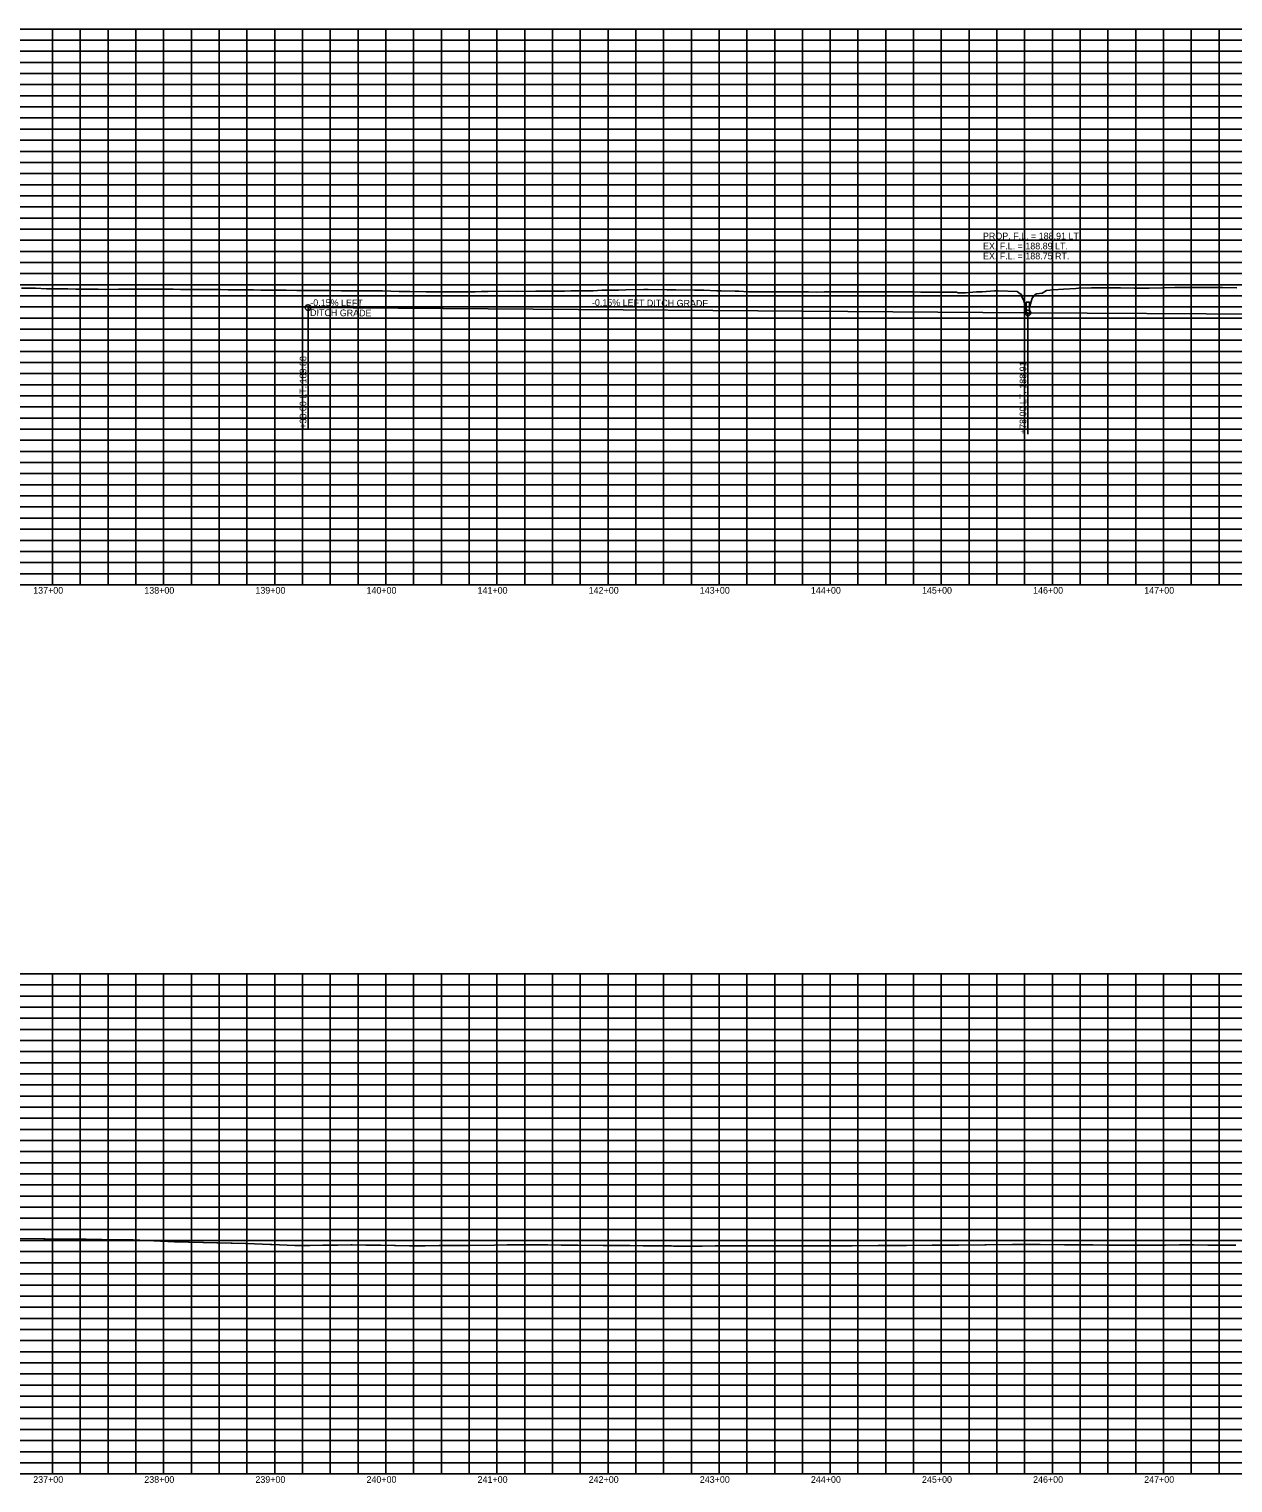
# Model space of a CAD drawing. Extents: x 1399671 to 1408349, y 1930471 to 1933387.
# Drawn here: x 1404003 to 1405087, y 1932071 to 1933379 of the extents above; entities that cross this region are included whole.
import ezdxf

# ---------------------------------------------------------------- set-up
doc = ezdxf.new("R2010")
doc.units = 0
for name, color, linetype in [('R_Drainage', 7, 'Continuous'), ('R_Exist Surface', 7, 'Continuous'), ('R_Grid', 7, 'Continuous'), ('R_Grid Annot', 7, 'Continuous'), ('R_Vert Alg', 7, 'Continuous'), ('R_Vert Alg Annot', 7, 'Continuous')]:
    doc.layers.add(name, color=color, linetype=linetype)

msp = doc.modelspace()

# ---------------------------------------------------------------- linework, layer by layer
at = {"layer": 'R_Drainage'}
msp.add_lwpolyline([(1404900.7, 1933122.8), (1404903.7, 1933122.8), (1404903.7, 1933132.8), (1404900.7, 1933132.8)], close=True, dxfattribs=at)
at = {"layer": 'R_Exist Surface'}
for points in [[(1403996.4, 1933145.6), (1404008.9, 1933145.5), (1404018.7, 1933145), (1404024.5, 1933145), (1404032, 1933144.9), (1404038.1, 1933144.8), (1404045.3, 1933144.7), (1404051.7, 1933144.6), (1404058.7, 1933144.5), (1404065.3, 1933144.5), (1404072, 1933144.4), (1404083.5, 1933144.5), (1404095.3, 1933144.5), (1404106.6, 1933144.6), (1404118.6, 1933144.6), (1404125.4, 1933144.5), (1404132.8, 1933144.5), (1404139.5, 1933144.4), (1404147, 1933144.4), (1404153.6, 1933144.4), (1404161.2, 1933144.3), (1404167.8, 1933144.3), (1404175.4, 1933144.2), (1404182.3, 1933144.1), (1404190.2, 1933144.1), (1404197, 1933144), (1404205, 1933143.9), (1404211.8, 1933143.8), (1404219.8, 1933143.8), (1404226.5, 1933143.7), (1404234.6, 1933143.6), (1404244, 1933143.5), (1404253.9, 1933143.5), (1404264, 1933143.4), (1404273.2, 1933143.4), (1404284.2, 1933143.2), (1404292.5, 1933143.2), (1404300.8, 1933143.2), (1404311.9, 1933143), (1404321.1, 1933143), (1404336.2, 1933142.6), (1404346, 1933142.6), (1404360.6, 1933142.2), (1404366.1, 1933142.2), (1404379.9, 1933142.2), (1404385.4, 1933142.2), (1404390.8, 1933142.3), (1404404.7, 1933142.2), (1404410, 1933142.6), (1404416.3, 1933142.5), (1404434.6, 1933142.7), (1404442.7, 1933142.5), (1404459.2, 1933142.7), (1404464.5, 1933142.7), (1404472.1, 1933142.8), (1404477.6, 1933142.8), (1404485, 1933142.9), (1404490.6, 1933143), (1404497.9, 1933143), (1404503.7, 1933143.1), (1404510.8, 1933143.1), (1404518.7, 1933143.6), (1404533.5, 1933143.8), (1404540.2, 1933144.1), (1404556.4, 1933144.4), (1404560.3, 1933144.3), (1404577.3, 1933144.1), (1404581.3, 1933144), (1404585.3, 1933143.9), (1404602, 1933143.7), (1404606.1, 1933143.6), (1404610.3, 1933143.6), (1404622.1, 1933143.2), (1404625.9, 1933143.2), (1404638.5, 1933142.8), (1404641.8, 1933142.8), (1404650.7, 1933142.3), (1404656.6, 1933142.3), (1404663.9, 1933142.3), (1404670.3, 1933142.2), (1404677.6, 1933142.2), (1404684.1, 1933142.2), (1404691.2, 1933142.1), (1404697.8, 1933142.1), (1404704.8, 1933142.1), (1404711.5, 1933142), (1404718.9, 1933142.1), (1404725.7, 1933142.1), (1404733, 1933142.1), (1404739.8, 1933142.1), (1404747.1, 1933142.2), (1404753.9, 1933142.2), (1404760.8, 1933142.2), (1404768.1, 1933142.2), (1404774.2, 1933142.2), (1404780.7, 1933142.2), (1404786.8, 1933142.1), (1404793.2, 1933142.1), (1404799.3, 1933142.1), (1404805.8, 1933142), (1404811.9, 1933142), (1404818.4, 1933142), (1404826.9, 1933141.9), (1404837.9, 1933141.8), (1404839.4, 1933141.4), (1404846, 1933141.4), (1404855.9, 1933142.1), (1404861.1, 1933142.1), (1404872.1, 1933143.1), (1404875.5, 1933143.1), (1404892.6, 1933142.6), (1404895.3, 1933140.3), (1404896.3, 1933139.9), (1404896.8, 1933138), (1404898.5, 1933134.2), (1404899.6, 1933130), (1404901.8, 1933128.8), (1404903.8, 1933129.4), (1404905, 1933133.5), (1404905.9, 1933136.4), (1404908.4, 1933139.4), (1404910, 1933140.5), (1404915, 1933141), (1404918.9, 1933143.4), (1404924.9, 1933144.1), (1404934.2, 1933144.6), (1404945.3, 1933145.1), (1404947.7, 1933145.4), (1404959.3, 1933145.8), (1404959.5, 1933145.8), (1404972.1, 1933145.8), (1404972.4, 1933145.8), (1404985, 1933145.7), (1404985.4, 1933145.7), (1404997.8, 1933145.6), (1404998.4, 1933145.6), (1405010.6, 1933145.5), (1405011.4, 1933145.5), (1405024.1, 1933145.8), (1405024.4, 1933145.8), (1405034.4, 1933146), (1405037.4, 1933146), (1405037.5, 1933146), (1405050.1, 1933146.1), (1405051, 1933146.1), (1405051.9, 1933146.1), (1405064.4, 1933146.1), (1405076.6, 1933146), (1405077.4, 1933146), (1405090.1, 1933145.8)], [(1403993.9, 1932290.5), (1404016.3, 1932290.2), (1404017.3, 1932290.2), (1404040, 1932289.9), (1404040.5, 1932289.9), (1404054, 1932289.7), (1404054.5, 1932289.7), (1404068.1, 1932289.5), (1404068.6, 1932289.5), (1404082.2, 1932289.3), (1404082.7, 1932289.3), (1404096.2, 1932289.1), (1404096.7, 1932289.1), (1404108.8, 1932288.6), (1404109.3, 1932288.6), (1404121.4, 1932288.1), (1404122, 1932288), (1404133.9, 1932287.5), (1404134.6, 1932287.5), (1404146.5, 1932287), (1404147.3, 1932287), (1404159.4, 1932286.7), (1404160.1, 1932286.7), (1404172.2, 1932286.4), (1404172.9, 1932286.4), (1404185.1, 1932286.1), (1404185.8, 1932286.1), (1404198, 1932285.9), (1404199.2, 1932285.8), (1404220.1, 1932285), (1404221.6, 1932285), (1404242.3, 1932284.1), (1404243.2, 1932284.1), (1404254.9, 1932284.2), (1404255.8, 1932284.2), (1404267.6, 1932284.4), (1404268.5, 1932284.4), (1404280.2, 1932284.5), (1404281.1, 1932284.5), (1404292.8, 1932284.6), (1404293.8, 1932284.6), (1404306.2, 1932284.4), (1404307.2, 1932284.4), (1404319.6, 1932284.3), (1404332.1, 1932284.1), (1404333, 1932284.1), (1404345.4, 1932283.9), (1404346.4, 1932283.9), (1404358.8, 1932283.9), (1404359.6, 1932283.9), (1404372.1, 1932284), (1404372.8, 1932284), (1404373.5, 1932284), (1404386, 1932284.1), (1404386.6, 1932284.1), (1404399.2, 1932284.2), (1404400.2, 1932284.2), (1404421.9, 1932284.5), (1404433.5, 1932284.6), (1404443.3, 1932284.8), (1404444.5, 1932284.8), (1404456.6, 1932284.7), (1404457.9, 1932284.7), (1404470.1, 1932284.6), (1404482.1, 1932284.5), (1404483.5, 1932284.5), (1404495.6, 1932284.4), (1404497.1, 1932284.4), (1404519.7, 1932284.2), (1404521.3, 1932284.2), (1404543.8, 1932284.1), (1404555.8, 1932283.9), (1404557.5, 1932283.9), (1404569.4, 1932283.8), (1404581.3, 1932283.7), (1404583.2, 1932283.6), (1404595, 1932283.5), (1404596.1, 1932283.5), (1404607.9, 1932283.6), (1404608.9, 1932283.6), (1404620.7, 1932283.7), (1404621.8, 1932283.7), (1404633.5, 1932283.8), (1404634.6, 1932283.8), (1404646.4, 1932283.9), (1404648.4, 1932283.9), (1404670.1, 1932283.9), (1404671.6, 1932283.9), (1404693.8, 1932283.9), (1404694.3, 1932283.9), (1404717.9, 1932283.9), (1404718.4, 1932283.9), (1404719, 1932283.9), (1404742.6, 1932283.8), (1404743.1, 1932283.8), (1404744.1, 1932283.8), (1404767.5, 1932284), (1404768.5, 1932284), (1404792, 1932284.1), (1404792.9, 1932284.1), (1404815.9, 1932284.3), (1404838.8, 1932284.5), (1404839.9, 1932284.5), (1404863.5, 1932284.8), (1404864.6, 1932284.8), (1404888.2, 1932285.1), (1404889.2, 1932285.1), (1404911.2, 1932285), (1404912.2, 1932284.9), (1404913.2, 1932284.9), (1404935.2, 1932284.8), (1404935.7, 1932284.8), (1404948, 1932284.7), (1404960.1, 1932284.6), (1404960.7, 1932284.6), (1404972.9, 1932284.5), (1404973.5, 1932284.5), (1404985.6, 1932284.5), (1404986.3, 1932284.5), (1404998.8, 1932284.5), (1404999.3, 1932284.5), (1404999.9, 1932284.5), (1405012.4, 1932284.5), (1405012.9, 1932284.5), (1405025.5, 1932284.5), (1405025.9, 1932284.5), (1405038.5, 1932284.6), (1405038.9, 1932284.6), (1405051.3, 1932284.6), (1405051.6, 1932284.6), (1405064.1, 1932284.5), (1405076.5, 1932284.5), (1405076.8, 1932284.5), (1405089.3, 1932284.5)]]:
    msp.add_lwpolyline(points, dxfattribs=at)
at = {"layer": 'R_Grid'}
for p, q in [((1400324.2, 1933378.6), (1408224.2, 1933378.6)), ((1400324.2, 1933378.6), (1408224.2, 1933378.6)), ((1404024.2, 1932878.6), (1404024.2, 1933378.6)), ((1404049.2, 1932878.6), (1404049.2, 1933378.6)), ((1404074.2, 1932878.6), (1404074.2, 1933378.6)), ((1404099.2, 1932878.6), (1404099.2, 1933378.6)), ((1404124.2, 1932878.6), (1404124.2, 1933378.6)), ((1404149.2, 1932878.6), (1404149.2, 1933378.6)), ((1404174.2, 1932878.6), (1404174.2, 1933378.6)), ((1404199.2, 1932878.6), (1404199.2, 1933378.6)), ((1404224.2, 1932878.6), (1404224.2, 1933378.6)), ((1404249.2, 1932878.6), (1404249.2, 1933378.6)), ((1404274.2, 1932878.6), (1404274.2, 1933378.6)), ((1404299.2, 1932878.6), (1404299.2, 1933378.6)), ((1404324.2, 1932878.6), (1404324.2, 1933378.6)), ((1404349.2, 1932878.6), (1404349.2, 1933378.6)), ((1404374.2, 1932878.6), (1404374.2, 1933378.6)), ((1404399.2, 1932878.6), (1404399.2, 1933378.6)), ((1404424.2, 1932878.6), (1404424.2, 1933378.6)), ((1404449.2, 1932878.6), (1404449.2, 1933378.6)), ((1404474.2, 1932878.6), (1404474.2, 1933378.6)), ((1404499.2, 1932878.6), (1404499.2, 1933378.6)), ((1404524.2, 1932878.6), (1404524.2, 1933378.6)), ((1404549.2, 1932878.6), (1404549.2, 1933378.6)), ((1404574.2, 1932878.6), (1404574.2, 1933378.6)), ((1404599.2, 1932878.6), (1404599.2, 1933378.6)), ((1404624.2, 1932878.6), (1404624.2, 1933378.6)), ((1404649.2, 1932878.6), (1404649.2, 1933378.6)), ((1404674.2, 1932878.6), (1404674.2, 1933378.6)), ((1404699.2, 1932878.6), (1404699.2, 1933378.6)), ((1404724.2, 1932878.6), (1404724.2, 1933378.6)), ((1404749.2, 1932878.6), (1404749.2, 1933378.6)), ((1404774.2, 1932878.6), (1404774.2, 1933378.6)), ((1404799.2, 1932878.6), (1404799.2, 1933378.6)), ((1404824.2, 1932878.6), (1404824.2, 1933378.6)), ((1404849.2, 1932878.6), (1404849.2, 1933378.6)), ((1404874.2, 1932878.6), (1404874.2, 1933378.6)), ((1404899.2, 1932878.6), (1404899.2, 1933378.6)), ((1404924.2, 1932878.6), (1404924.2, 1933378.6)), ((1404949.2, 1932878.6), (1404949.2, 1933378.6)), ((1404974.2, 1932878.6), (1404974.2, 1933378.6)), ((1404999.2, 1932878.6), (1404999.2, 1933378.6)), ((1405024.2, 1932878.6), (1405024.2, 1933378.6)), ((1405049.2, 1932878.6), (1405049.2, 1933378.6)), ((1405074.2, 1932878.6), (1405074.2, 1933378.6)), ((1400324.2, 1933368.6), (1408224.2, 1933368.6)), ((1400324.2, 1933358.6), (1408224.2, 1933358.6)), ((1400324.2, 1933348.6), (1408224.2, 1933348.6)), ((1400324.2, 1933338.6), (1408224.2, 1933338.6)), ((1400324.2, 1933328.6), (1408224.2, 1933328.6)), ((1400324.2, 1933318.6), (1408224.2, 1933318.6)), ((1400324.2, 1933308.6), (1408224.2, 1933308.6)), ((1400324.2, 1933298.6), (1408224.2, 1933298.6)), ((1400324.2, 1933288.6), (1408224.2, 1933288.6)), ((1400324.2, 1933278.6), (1408224.2, 1933278.6)), ((1400324.2, 1933268.6), (1408224.2, 1933268.6)), ((1400324.2, 1933258.6), (1408224.2, 1933258.6)), ((1400324.2, 1933248.6), (1408224.2, 1933248.6)), ((1400324.2, 1933238.6), (1408224.2, 1933238.6)), ((1400324.2, 1933228.6), (1408224.2, 1933228.6)), ((1400324.2, 1933218.6), (1408224.2, 1933218.6)), ((1400324.2, 1933208.6), (1408224.2, 1933208.6)), ((1400324.2, 1933198.6), (1408224.2, 1933198.6)), ((1400324.2, 1933188.6), (1408224.2, 1933188.6)), ((1400324.2, 1933178.6), (1408224.2, 1933178.6)), ((1400324.2, 1933168.6), (1408224.2, 1933168.6)), ((1400324.2, 1933158.6), (1408224.2, 1933158.6)), ((1400324.2, 1933148.6), (1408224.2, 1933148.6)), ((1400324.2, 1933138.6), (1408224.2, 1933138.6)), ((1400324.2, 1933128.6), (1408224.2, 1933128.6)), ((1400324.2, 1933118.6), (1408224.2, 1933118.6)), ((1400324.2, 1933108.6), (1408224.2, 1933108.6)), ((1400324.2, 1933098.6), (1408224.2, 1933098.6)), ((1400324.2, 1933088.6), (1408224.2, 1933088.6)), ((1400324.2, 1933078.6), (1408224.2, 1933078.6)), ((1400324.2, 1933068.6), (1408224.2, 1933068.6)), ((1400324.2, 1933058.6), (1408224.2, 1933058.6)), ((1400324.2, 1933048.6), (1408224.2, 1933048.6)), ((1400324.2, 1933038.6), (1408224.2, 1933038.6)), ((1400324.2, 1933028.6), (1408224.2, 1933028.6)), ((1400324.2, 1933018.6), (1408224.2, 1933018.6)), ((1400324.2, 1933008.6), (1408224.2, 1933008.6)), ((1400324.2, 1932998.6), (1408224.2, 1932998.6)), ((1400324.2, 1932988.6), (1408224.2, 1932988.6)), ((1400324.2, 1932978.6), (1408224.2, 1932978.6)), ((1400324.2, 1932968.6), (1408224.2, 1932968.6)), ((1400324.2, 1932958.6), (1408224.2, 1932958.6)), ((1400324.2, 1932948.6), (1408224.2, 1932948.6)), ((1400324.2, 1932938.6), (1408224.2, 1932938.6)), ((1400324.2, 1932928.6), (1408224.2, 1932928.6)), ((1400324.2, 1932918.6), (1408224.2, 1932918.6)), ((1400324.2, 1932908.6), (1408224.2, 1932908.6)), ((1400324.2, 1932898.6), (1408224.2, 1932898.6)), ((1400324.2, 1932888.6), (1408224.2, 1932888.6)), ((1400324.2, 1932878.6), (1408224.2, 1932878.6)), ((1400324.2, 1932528.6), (1407124.2, 1932528.6)), ((1400324.2, 1932528.6), (1407124.2, 1932528.6)), ((1404024.2, 1932078.6), (1404024.2, 1932528.6)), ((1404049.2, 1932078.6), (1404049.2, 1932528.6)), ((1404074.2, 1932078.6), (1404074.2, 1932528.6)), ((1404099.2, 1932078.6), (1404099.2, 1932528.6)), ((1404124.2, 1932078.6), (1404124.2, 1932528.6)), ((1404149.2, 1932078.6), (1404149.2, 1932528.6)), ((1404174.2, 1932078.6), (1404174.2, 1932528.6)), ((1404199.2, 1932078.6), (1404199.2, 1932528.6)), ((1404224.2, 1932078.6), (1404224.2, 1932528.6)), ((1404249.2, 1932078.6), (1404249.2, 1932528.6)), ((1404274.2, 1932078.6), (1404274.2, 1932528.6)), ((1404299.2, 1932078.6), (1404299.2, 1932528.6)), ((1404324.2, 1932078.6), (1404324.2, 1932528.6)), ((1404349.2, 1932078.6), (1404349.2, 1932528.6)), ((1404374.2, 1932078.6), (1404374.2, 1932528.6)), ((1404399.2, 1932078.6), (1404399.2, 1932528.6)), ((1404424.2, 1932078.6), (1404424.2, 1932528.6)), ((1404449.2, 1932078.6), (1404449.2, 1932528.6)), ((1404474.2, 1932078.6), (1404474.2, 1932528.6)), ((1404499.2, 1932078.6), (1404499.2, 1932528.6)), ((1404524.2, 1932078.6), (1404524.2, 1932528.6)), ((1404549.2, 1932078.6), (1404549.2, 1932528.6)), ((1404574.2, 1932078.6), (1404574.2, 1932528.6)), ((1404599.2, 1932078.6), (1404599.2, 1932528.6)), ((1404624.2, 1932078.6), (1404624.2, 1932528.6)), ((1404649.2, 1932078.6), (1404649.2, 1932528.6)), ((1404674.2, 1932078.6), (1404674.2, 1932528.6)), ((1404699.2, 1932078.6), (1404699.2, 1932528.6)), ((1404724.2, 1932078.6), (1404724.2, 1932528.6)), ((1404749.2, 1932078.6), (1404749.2, 1932528.6)), ((1404774.2, 1932078.6), (1404774.2, 1932528.6)), ((1404799.2, 1932078.6), (1404799.2, 1932528.6)), ((1404824.2, 1932078.6), (1404824.2, 1932528.6)), ((1404849.2, 1932078.6), (1404849.2, 1932528.6)), ((1404874.2, 1932078.6), (1404874.2, 1932528.6)), ((1404899.2, 1932078.6), (1404899.2, 1932528.6)), ((1404924.2, 1932078.6), (1404924.2, 1932528.6)), ((1404949.2, 1932078.6), (1404949.2, 1932528.6)), ((1404974.2, 1932078.6), (1404974.2, 1932528.6)), ((1404999.2, 1932078.6), (1404999.2, 1932528.6)), ((1405024.2, 1932078.6), (1405024.2, 1932528.6)), ((1405049.2, 1932078.6), (1405049.2, 1932528.6)), ((1405074.2, 1932078.6), (1405074.2, 1932528.6)), ((1400324.2, 1932518.6), (1407124.2, 1932518.6)), ((1400324.2, 1932508.6), (1407124.2, 1932508.6)), ((1400324.2, 1932498.6), (1407124.2, 1932498.6)), ((1400324.2, 1932488.6), (1407124.2, 1932488.6)), ((1400324.2, 1932478.6), (1407124.2, 1932478.6)), ((1400324.2, 1932468.6), (1407124.2, 1932468.6)), ((1400324.2, 1932458.6), (1407124.2, 1932458.6)), ((1400324.2, 1932448.6), (1407124.2, 1932448.6)), ((1400324.2, 1932438.6), (1407124.2, 1932438.6)), ((1400324.2, 1932428.6), (1407124.2, 1932428.6)), ((1400324.2, 1932418.6), (1407124.2, 1932418.6)), ((1400324.2, 1932408.6), (1407124.2, 1932408.6)), ((1400324.2, 1932398.6), (1407124.2, 1932398.6)), ((1400324.2, 1932388.6), (1407124.2, 1932388.6)), ((1400324.2, 1932378.6), (1407124.2, 1932378.6)), ((1400324.2, 1932368.6), (1407124.2, 1932368.6)), ((1400324.2, 1932358.6), (1407124.2, 1932358.6)), ((1400324.2, 1932348.6), (1407124.2, 1932348.6)), ((1400324.2, 1932338.6), (1407124.2, 1932338.6)), ((1400324.2, 1932328.6), (1407124.2, 1932328.6)), ((1400324.2, 1932318.6), (1407124.2, 1932318.6)), ((1400324.2, 1932308.6), (1407124.2, 1932308.6)), ((1400324.2, 1932298.6), (1407124.2, 1932298.6)), ((1400324.2, 1932288.6), (1407124.2, 1932288.6)), ((1400324.2, 1932278.6), (1407124.2, 1932278.6)), ((1400324.2, 1932268.6), (1407124.2, 1932268.6)), ((1400324.2, 1932258.6), (1407124.2, 1932258.6)), ((1400324.2, 1932248.6), (1407124.2, 1932248.6)), ((1400324.2, 1932238.6), (1407124.2, 1932238.6)), ((1400324.2, 1932228.6), (1407124.2, 1932228.6)), ((1400324.2, 1932218.6), (1407124.2, 1932218.6)), ((1400324.2, 1932208.6), (1407124.2, 1932208.6)), ((1400324.2, 1932198.6), (1407124.2, 1932198.6)), ((1400324.2, 1932188.6), (1407124.2, 1932188.6)), ((1400324.2, 1932178.6), (1407124.2, 1932178.6)), ((1400324.2, 1932168.6), (1407124.2, 1932168.6)), ((1400324.2, 1932158.6), (1407124.2, 1932158.6)), ((1400324.2, 1932148.6), (1407124.2, 1932148.6)), ((1400324.2, 1932138.6), (1407124.2, 1932138.6)), ((1400324.2, 1932128.6), (1407124.2, 1932128.6)), ((1400324.2, 1932118.6), (1407124.2, 1932118.6)), ((1400324.2, 1932108.6), (1407124.2, 1932108.6)), ((1400324.2, 1932098.6), (1407124.2, 1932098.6)), ((1400324.2, 1932088.6), (1407124.2, 1932088.6)), ((1400324.2, 1932078.6), (1407124.2, 1932078.6))]:
    msp.add_line(p, q, dxfattribs=at)
at = {"layer": 'R_Vert Alg'}
for p, q in [((1404254.2, 1933128), (1404902.2, 1933123.2)), ((1404902.2, 1933123.2), (1405784.2, 1933119.2))]:
    msp.add_line(p, q, dxfattribs=at)
at = {"layer": 'R_Vert Alg Annot'}
for p, q in [((1404254.2, 1933128), (1404254.2, 1933103)), ((1404902.2, 1933123.2), (1404902.2, 1933098.2)), ((1404254.2, 1933103), (1404254.2, 1933019)), ((1404902.2, 1933098.2), (1404902.2, 1933014.2))]:
    msp.add_line(p, q, dxfattribs=at)
for centre in [(1404254.2, 1933128), (1404902.2, 1933123.2)]:
    msp.add_circle(centre, 2.5, dxfattribs=at)

# ---------------------------------------------------------------- texts
at = {"layer": 'R_Grid Annot'}
for s, p in [('137+00', (1404006.8, 1932870.6)), ('138+00', (1404106.8, 1932870.6)), ('139+00', (1404206.8, 1932870.6)), ('140+00', (1404306.8, 1932870.6)), ('141+00', (1404406.8, 1932870.6)), ('142+00', (1404506.8, 1932870.6)), ('143+00', (1404606.8, 1932870.6)), ('144+00', (1404706.8, 1932870.6)), ('145+00', (1404806.8, 1932870.6)), ('146+00', (1404906.8, 1932870.6)), ('147+00', (1405006.8, 1932870.6)), ('237+00', (1404006.8, 1932070.6)), ('238+00', (1404106.8, 1932070.6)), ('239+00', (1404206.8, 1932070.6)), ('240+00', (1404306.8, 1932070.6)), ('241+00', (1404406.8, 1932070.6)), ('242+00', (1404506.8, 1932070.6)), ('243+00', (1404606.8, 1932070.6)), ('244+00', (1404706.8, 1932070.6)), ('245+00', (1404806.8, 1932070.6)), ('246+00', (1404906.8, 1932070.6)), ('247+00', (1405006.8, 1932070.6))]:
    msp.add_text(s, height=6, dxfattribs=at).set_placement(p)
at = {"layer": 'R_Vert Alg Annot'}
for s, p in [('PROP. F.L. = 188.91 LT.', (1404861.7, 1933189.4)), ('EX. F.L. = 188.89 LT.', (1404861.7, 1933180.4)), ('EX. F.L. = 188.75 RT.', (1404861.7, 1933171.4))]:
    msp.add_text(s, height=6, dxfattribs=at).set_placement(p)
for s, rotation, p in [('-0.15% LEFT', 359.5712, (1404256.2, 1933129.5)), ('-0.15% LEFT DITCH GRADE', 359.5712, (1404509.7, 1933129.6)), ('DITCH GRADE', 359.5712, (1404256, 1933120.5)), ('+30.00 LT. 189.88', 90, (1404252.7, 1933019)), ('+78.00 LT. 188.91', 90, (1404900.7, 1933014.2))]:
    msp.add_text(s, height=6, rotation=rotation, dxfattribs=at).set_placement(p)

doc.saveas('drawing.dxf')
